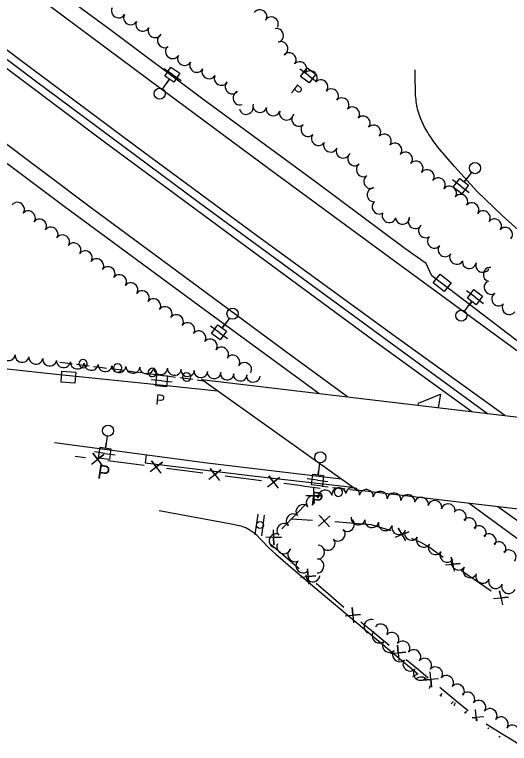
# Model space of a CAD drawing. Extents: x 1746010 to 1754829, y 655801 to 663091.
# Drawn here: x 1750070 to 1750426, y 659823 to 660347 of the extents above; entities that cross this region are included whole.
import ezdxf

# ---------------------------------------------------------------- set-up
doc = ezdxf.new("R2010")
doc.units = 0
for name, color, linetype in [('SURVEY - AERIAL SURVEY - Photo Control - Points - Elevations', 7, 'Continuous'), ('SURVEY - AERIAL SURVEY - Photo Control - Points - Locators', 7, 'Continuous'), ('SURVEY - AERIAL SURVEY - Photo Control - Points - Numbers', 7, 'Continuous'), ('SURVEY - AERIAL SURVEY - Photo Control with Text', 7, 'Continuous'), ('SURVEY - CENTERLINE - Existing Roads - Development', 7, 'Continuous'), ('SURVEY - CENTERLINE - Existing Roads Curve Text', 7, 'Continuous'), ('SURVEY - CENTERLINE - Existing Roads Text', 7, 'Continuous'), ('SURVEY - CENTERLINE - Preliminary - Development', 7, 'Continuous')]:
    doc.layers.add(name, color=color, linetype=linetype)

msp = doc.modelspace()

# ---------------------------------------------------------------- linework, layer by layer
at = {"layer": 'SURVEY - AERIAL SURVEY - Photo Control - Points - Elevations'}
for points in [[(1750204.41, 660084.58), (1750567.39, 660041.45), (1750676.22, 659962.69), (1750316.04, 660004.98)], [(1750316.04, 660004.98), (1750204.41, 660084.58)]]:
    msp.add_lwpolyline(points, dxfattribs=at)
at = {"layer": 'SURVEY - AERIAL SURVEY - Photo Control - Points - Locators'}
for points in [[(1749387.11, 660899.35), (1749486.53, 660821.3), (1749560.37, 660763.13), (1749636.02, 660704.45), (1749732.4, 660629.58), (1749833.07, 660551.99), (1749920.33, 660484.88), (1750008.5, 660418.55), (1750084.45, 660361.56), (1750166.82, 660299.99), (1750252.84, 660236.3), (1750339.47, 660172.61), (1750424.46, 660110.17), (1750505.09, 660051.79), (1750510.03, 660048.27)], [(1750422.34, 660058.69), (1750341.81, 660116.67), (1750243.85, 660188.2), (1750158.07, 660251.54), (1750079.76, 660310), (1749998.95, 660370.82), (1749924.19, 660427.29), (1749840.05, 660491.49), (1749747.97, 660561.59), (1749667.56, 660623.87), (1749593.96, 660681.21), (1749510.38, 660746.53), (1749431.04, 660809.06), (1749359.66, 660865.36)], [(1749353.21, 660856.72), (1749450.09, 660780.53), (1749529.69, 660717.36), (1749638.4, 660632.78), (1749725.25, 660565.49), (1749826.74, 660487.69), (1749908.21, 660425.76), (1750015.78, 660344.74), (1750134.74, 660255.49), (1750241.73, 660176.3), (1750327.29, 660113.27), (1750398.53, 660061.52)], [(1750288.61, 660074.58), (1750206.58, 660134.59), (1750105.78, 660208.88), (1750014.16, 660277.34), (1749883.11, 660375.92), (1749790.93, 660445.43), (1749702.19, 660513.29), (1749634.54, 660565.49), (1749547.88, 660632.78), (1749453.06, 660707.08), (1749311.71, 660816.35)], [(1750309.34, 660072.12), (1750268.26, 660102.16), (1750202.16, 660151.04), (1750125.31, 660207.81), (1750054.71, 660260.76), (1749978.89, 660317.54), (1749904.25, 660374.13), (1749807.5, 660447.32), (1749742.59, 660496.65), (1749689.97, 660537.57), (1749628.45, 660585.34), (1749555.8, 660641.5), (1749484.89, 660697.07), (1749405.47, 660759.79), (1749328.25, 660820.51)], [(1750358.12, 660290), (1750357.98, 660303.43), (1750358.02, 660307.18)], [(1750438.83, 660185.91), (1750420.38, 660202.58), (1750402.21, 660219.96), (1750386.13, 660237.65), (1750374.12, 660251.65)], [(1750519.47, 660047.15), (1750452.55, 660096.14), (1750387.84, 660145.49), (1750369.91, 660159), (1750365.71, 660168.08)], [(1750007.27, 660098.55), (1750097.85, 660088.69), (1750163.16, 660081.99), (1750215.81, 660076.45)], [(1750304.68, 660013.08), (1750208.54, 660024.58), (1750098.73, 660039.05)], [(1750164.64, 660030.36), (1750163.84, 660024.63), (1750243.12, 660015.16), (1750312.84, 660007.26)], [(1750445.81, 659959.59), (1750396.7, 659995.51)], [(1750464.75, 659959.09), (1750428.94, 659984.64), (1750417.4, 659993.08)], [(1750174.01, 659990.42), (1750227.08, 659980.67)], [(1750236.21, 659978.21), (1750238.66, 659976.87), (1750242.86, 659973.96), (1750247.83, 659968.99), (1750252.49, 659963.92), (1750257.85, 659959.09), (1750269.97, 659948.61), (1750288.83, 659932.39), (1750322.85, 659903.93), (1750359.72, 659873.19)], [(1750359.72, 659873.19), (1750355.88, 659870.98)]]:
    msp.add_lwpolyline(points, dxfattribs=at)
for points in [[(1750374.12, 660251.65), (1750366.96, 660262.02), (1750359.66, 660278.87), (1750358.12, 660290)], [(1750227.08, 659980.67), (1750231.41, 659979.69), (1750236.21, 659978.21)]]:
    msp.add_spline(points, degree=3, dxfattribs=at)
at = {"layer": 'SURVEY - AERIAL SURVEY - Photo Control - Points - Numbers'}
for points in [[(1750365.71, 660168.08), (1750350.37, 660178.69), (1750287.2, 660225.82), (1750205.37, 660286.01), (1750139.45, 660335.41), (1750086.68, 660374.49), (1749983.6, 660451.73), (1749923.2, 660497.58), (1749846.86, 660555.87), (1749777.3, 660609.82), (1749717.93, 660655.7), (1749636.62, 660718.64), (1749570.63, 660769.87), (1749510.15, 660817.71), (1749441.97, 660871.04), (1749371.15, 660927.67)], [(1749348.39, 660867.21), (1749450.14, 660787.41), (1749578.82, 660686.52), (1749682.3, 660605.65), (1749779.99, 660530.78), (1749879.01, 660455.62), (1749985.38, 660374.75), (1750084.31, 660300.06), (1750202.67, 660211.89), (1750354.74, 660100.39), (1750409.77, 660060.18)], [(1750106.76, 660096.28), (1750102.61, 660096.79)], [(1750111.43, 660095.69), (1750106.76, 660096.28)], [(1750123.73, 660094.16), (1750114.6, 660095.3)], [(1750131.57, 660093.18), (1750126.91, 660093.76)], [(1750136.24, 660092.6), (1750131.57, 660093.18)], [(1750148.53, 660091.01), (1750139.41, 660092.2)], [(1750156.37, 660089.98), (1750151.71, 660090.59)], [(1750161.03, 660089.37), (1750156.37, 660089.98)], [(1750173.32, 660087.76), (1750164.2, 660088.96)], [(1750181.16, 660086.74), (1750176.5, 660087.35)], [(1750185.81, 660086.13), (1750181.16, 660086.74)], [(1750198.11, 660084.52), (1750188.99, 660085.71)], [(1750205.94, 660083.49), (1750201.28, 660084.1)], [(1750290.74, 660008.01), (1750295.4, 660007.45)], [(1750298.58, 660007.07), (1750307.7, 660005.98)], [(1750310.87, 660005.6), (1750315.54, 660005.05)], [(1750315.54, 660005.05), (1750316.04, 660004.98)]]:
    msp.add_lwpolyline(points, dxfattribs=at)
for centre, start, end in [((1750119.38, 660096.03), 3.5727, 3.5588), ((1750144.22, 660092.9), 3.173, 3.159), ((1750169.01, 660089.65), 3.173, 3.159), ((1750193.8, 660086.41), 3.173, 3.159), ((1750302.74, 660003.55), 196.4762, 196.4622)]:
    msp.add_arc(centre, 3, start, end, dxfattribs=at)
at = {"layer": 'SURVEY - AERIAL SURVEY - Photo Control with Text'}
for p, q in [((1750243, 659972.93), (1750245, 659987.8)), ((1750247.76, 659972.29), (1750249.76, 659987.16))]:
    msp.add_line(p, q, dxfattribs=at)
msp.add_lwpolyline([(1750360.15, 660066.08), (1750360.28, 660067.51), (1750376.1, 660074.16), (1750374.34, 660064.39)], dxfattribs=at)
msp.add_circle((1750246.38, 659980.04), 2.54, dxfattribs=at)
at = {"layer": 'SURVEY - CENTERLINE - Existing Roads - Development'}
for points in [[(1750125.31, 660023.86), (1750134.13, 660030.66), (1750129.77, 660027.26), (1750126.29, 660031.68), (1750133.15, 660022.84)], [(1750113.6, 660029.45), (1750121.16, 660028.47)], [(1750137.12, 660026.4), (1750148.43, 660024.94)], [(1750148.43, 660024.94), (1750163.3, 660023.01)], [(1750167.46, 660018.4), (1750176.27, 660025.21), (1750171.91, 660021.8), (1750168.44, 660026.22), (1750175.29, 660017.39)], [(1750179.26, 660020.95), (1750190.56, 660019.48)], [(1750190.56, 660019.48), (1750205.44, 660017.56)], [(1750209.59, 660012.95), (1750218.41, 660019.75), (1750214.05, 660016.34), (1750210.58, 660020.77), (1750217.43, 660011.93)], [(1750221.4, 660015.49), (1750232.71, 660014.03)], [(1750232.71, 660014.03), (1750247.58, 660012.1)], [(1750251.74, 660007.49), (1750260.55, 660014.3), (1750256.19, 660010.89), (1750252.72, 660015.31), (1750259.57, 660006.48)], [(1750263.54, 660010.03), (1750274.85, 660008.57)], [(1750274.85, 660008.57), (1750278.9, 660008.05), (1750289.7, 660006.61)], [(1750284.85, 660006.54), (1750285.31, 659995.58), (1750285.04, 660001.02), (1750290.68, 660001.13), (1750279.47, 660000.99)], [(1750280.08, 659995.76), (1750272.33, 659987.75)], [(1750272.33, 659987.75), (1750262.12, 659977.21)], [(1750269.14, 659984.45), (1750284.11, 659983.55)], [(1750288.56, 659979.18), (1750296.93, 659986.69), (1750292.79, 659982.93), (1750289.04, 659987.17), (1750296.44, 659978.7)], [(1750300.18, 659982.56), (1750311.55, 659981.66)], [(1750311.55, 659981.66), (1750325.98, 659980.52)], [(1750325.98, 659980.52), (1750338.36, 659976.86), (1750340.31, 659976.17)], [(1750343.61, 659971.21), (1750353.26, 659975.22), (1750348.48, 659973.2), (1750345.81, 659977.85), (1750351.06, 659968.59)], [(1750255.94, 659976.68), (1750256.4, 659965.72), (1750256.13, 659971.17), (1750261.77, 659971.27), (1750250.56, 659971.14)], [(1750355.38, 659970.56), (1750361.73, 659967.77), (1750365.58, 659965.55)], [(1750254.54, 659966.02), (1750263.16, 659958.56)], [(1750365.58, 659965.55), (1750368.24, 659964.01), (1750377.91, 659957.05)], [(1750263.16, 659958.56), (1750274.51, 659948.76)], [(1750379.58, 659951.44), (1750390.18, 659952.41), (1750384.92, 659951.9), (1750383.77, 659957.03), (1750385.99, 659946.83)], [(1750275.41, 659942.62), (1750286.57, 659943.43), (1750281.03, 659942.99), (1750280.6, 659948.6), (1750281.39, 659937.45)], [(1750390.97, 659947.65), (1750395.32, 659944.52), (1750400.28, 659941.11)], [(1750400.28, 659941.11), (1750412.58, 659932.64)], [(1750286.7, 659938.23), (1750295.32, 659930.77)], [(1750295.32, 659930.77), (1750306.67, 659920.97)], [(1750414.27, 659927.15), (1750425, 659928.23), (1750419.67, 659927.66), (1750418.51, 659932.69), (1750420.75, 659922.69)], [(1750307.57, 659914.83), (1750318.73, 659915.64), (1750313.19, 659915.2), (1750312.75, 659920.81), (1750313.55, 659909.66)], [(1750318.88, 659910.49), (1750327.62, 659903.25)], [(1750327.62, 659903.25), (1750339.12, 659893.72)], [(1750340.09, 659887.65), (1750351.28, 659888.66), (1750345.72, 659888.12), (1750345.22, 659893.68), (1750346.14, 659882.64)], [(1750351.46, 659883.5), (1750360.2, 659876.26)], [(1750360.2, 659876.26), (1750367.35, 659870.33)], [(1750374.69, 659869.54), (1750363.49, 659868.48), (1750369.05, 659869.04), (1750369.55, 659863.41), (1750368.63, 659874.61)], [(1750387.16, 659853.77), (1750375.66, 659863.39)], [(1750395.91, 659846.46), (1750387.16, 659853.77)], [(1750401.88, 659839.37), (1750401.22, 659847.36)], [(1750398.78, 659841.5), (1750401.65, 659841.79), (1750401.86, 659839.38)], [(1750407.28, 659842.29), (1750398.8, 659841.48)], [(1750421.64, 659829.1), (1750408.88, 659836.99)], [(1750431.32, 659823.1), (1750425.59, 659826.66), (1750421.64, 659829.1)]]:
    msp.add_lwpolyline(points, dxfattribs=at)
at = {"layer": 'SURVEY - CENTERLINE - Existing Roads Curve Text'}
for p, q in [((1750183.51, 660303.76), (1750177.27, 660307.93)), ((1750280.98, 660303.2), (1750274.99, 660307.73)), ((1750183.51, 660303.76), (1750189.74, 660299.59)), ((1750280.98, 660303.2), (1750286.96, 660298.68)), ((1750176.5, 660293.28), (1750181.34, 660300.52)), ((1750181.12, 660300.19), (1750179.34, 660297.52)), ((1750398.47, 660233.43), (1750393.15, 660226.54)), ((1750393.4, 660226.86), (1750395.35, 660229.39)), ((1750390.77, 660223.46), (1750384.83, 660228.04)), ((1750390.77, 660223.46), (1750396.71, 660218.87)), ((1750400.9, 660143.73), (1750394.89, 660148.22)), ((1750393.36, 660133.63), (1750398.57, 660140.61)), ((1750398.33, 660140.29), (1750396.41, 660137.72)), ((1750400.9, 660143.73), (1750406.91, 660139.25)), ((1750224.42, 660128.69), (1750219.32, 660121.65)), ((1750219.55, 660121.97), (1750221.43, 660124.56)), ((1750217.03, 660118.49), (1750210.95, 660122.89)), ((1750217.03, 660118.49), (1750223.1, 660114.09)), ((1750175.8, 660083.64), (1750168.33, 660084.33)), ((1750175.8, 660083.64), (1750183.27, 660082.95)), ((1750136.74, 660043.97), (1750135.5, 660035.36)), ((1750135.56, 660035.75), (1750136.01, 660038.92)), ((1750134.94, 660031.5), (1750127.52, 660032.57)), ((1750134.94, 660031.5), (1750142.37, 660030.42)), ((1750289.27, 660024.78), (1750288.26, 660016.14)), ((1750288.3, 660016.54), (1750288.68, 660019.72)), ((1750287.8, 660012.27), (1750280.35, 660013.14)), ((1750287.8, 660012.27), (1750295.25, 660011.39))]:
    msp.add_line(p, q, dxfattribs=at)
for points in [[(1750188.92, 660304.83), (1750184.58, 660298.35), (1750178.09, 660302.69), (1750182.43, 660309.17)], [(1750280.22, 660308.67), (1750286.44, 660303.96), (1750281.74, 660297.74), (1750275.51, 660302.44)], [(1750385.3, 660222.76), (1750390.07, 660228.93), (1750396.24, 660224.16), (1750391.47, 660217.99)], [(1750406.36, 660144.53), (1750401.69, 660138.28), (1750395.44, 660142.94), (1750400.11, 660149.19)], [(1750211.58, 660117.62), (1750216.16, 660123.94), (1750222.48, 660119.36), (1750217.9, 660113.04)], [(1750172.28, 660087.88), (1750180.04, 660087.17), (1750179.33, 660079.4), (1750171.56, 660080.11)], [(1750130.53, 660028.19), (1750131.64, 660035.91), (1750139.36, 660034.8), (1750138.25, 660027.08)], [(1750283.47, 660008.85), (1750284.38, 660016.6), (1750292.13, 660015.69), (1750291.22, 660007.94)]]:
    msp.add_lwpolyline(points, close=True, dxfattribs=at)
for centre in [(1750174.33, 660290.04), (1750400.86, 660236.52), (1750226.71, 660131.85), (1750391.03, 660130.51), (1750137.3, 660047.83), (1750289.73, 660028.66)]:
    msp.add_circle(centre, 4, dxfattribs=at)
at = {"layer": 'SURVEY - CENTERLINE - Existing Roads Text'}
for centre, major_axis, start_param, end_param in [((1750144.65, 660349.24), (-4.35, 2.46), 0, 3.141593), ((1750246.46, 660345.55), (4.23, -2.67), 0, 3.141593), ((1750153.35, 660344.32), (-4.35, 2.46), 0, 3.141593), ((1750254.66, 660340.37), (4.23, -2.67), 0, 3.141593), ((1750162.15, 660339.63), (-4.44, 2.3), 0, 3.141593), ((1750170.99, 660335.05), (-4.44, 2.3), 0, 3.141593), ((1750258.52, 660331.86), (1.24, -4.84), 0, 3.141593), ((1750177.61, 660327.97), (-2.74, 4.18), 0, 3.141593), ((1750261.74, 660322.51), (2.12, -4.53), 0, 3.141593), ((1750183.44, 660319.97), (-4.35, 2.46), 0, 3.141593), ((1750267.53, 660314.64), (3.8, -3.25), 0, 3.141593), ((1750192.14, 660315.06), (-4.35, 2.46), 0, 3.141593), ((1750200.85, 660310.14), (-4.35, 2.46), 0, 3.141593), ((1750275.13, 660308.14), (3.8, -3.25), 0, 3.141593), ((1750209.65, 660305.45), (-4.43, 2.33), 0, 3.141593), ((1750218.48, 660300.81), (-4.43, 2.33), 0, 3.141593), ((1750282.72, 660301.64), (3.8, -3.25), 0, 3.141593), ((1750226.35, 660294.71), (-3.81, 3.24), 0, 3.141593), ((1750290.32, 660295.13), (3.8, -3.25), 0, 3.141593), ((1750297.91, 660288.63), (3.8, -3.25), 0, 3.141593), ((1750231.81, 660286.85), (-1.83, 4.65), 0, 3.141593), ((1750305.51, 660282.13), (3.8, -3.25), 0, 3.141593), ((1750246.26, 660281.21), (-4.85, 1.21), 0, 3.141593), ((1750236.54, 660279.86), (-4.89, -1.05), 0, 3.141593), ((1750255.9, 660278.79), (-4.85, 1.21), 0, 3.141593), ((1750265.35, 660275.79), (-4.71, 1.69), 0, 3.141593), ((1750313.1, 660275.63), (3.8, -3.25), 0, 3.141593), ((1750274.07, 660271.5), (-3.34, 3.72), 0, 3.141593), ((1750320.7, 660269.13), (3.8, -3.25), 0, 3.141593), ((1750280.74, 660264.06), (-3.34, 3.72), 0, 3.141593), ((1750328.3, 660262.64), (3.8, -3.25), 0, 3.141593), ((1750288.3, 660257.53), (-3.87, 3.17), 0, 3.141593), ((1750335.9, 660256.15), (3.8, -3.25), 0, 3.141593), ((1750297.05, 660252.81), (-4.53, 2.11), 0, 3.141593), ((1750343.5, 660249.66), (3.8, -3.25), 0, 3.141593), ((1750306.04, 660248.46), (-4.37, 2.44), 0, 3.141593), ((1750314.27, 660243.08), (-3.11, 3.92), 0, 3.141593), ((1750351.1, 660243.17), (3.8, -3.25), 0, 3.141593), ((1750320.42, 660235.2), (-2.67, 4.23), 0, 3.141593), ((1750358.71, 660236.68), (3.8, -3.25), 0, 3.141593), ((1750366.64, 660230.6), (4.03, -2.97), 0, 3.141593), ((1750325.76, 660226.75), (-2.67, 4.23), 0, 3.141593), ((1750374.69, 660224.67), (4.03, -2.97), 0, 3.141593), ((1750382.74, 660218.74), (4.03, -2.97), 0, 3.141593), ((1750328.17, 660217.28), (-0.7, 4.95), 0, 3.141593), ((1750390.79, 660212.81), (4.03, -2.97), 0, 3.141593), ((1750072.33, 660207.14), (3.93, -3.1), 0, 3.141593), ((1750331.84, 660208.38), (-3.05, 3.96), 0, 3.141593), ((1750398.85, 660206.9), (4.05, -2.93), 0, 3.141593), ((1750080.19, 660200.95), (3.93, -3.1), 0, 3.141593), ((1750339.17, 660202.09), (-4.63, 1.89), 0, 3.141593), ((1750406.94, 660201.05), (4.05, -2.93), 0, 3.141593), ((1750088.26, 660195.07), (4.11, -2.85), 0, 3.141593), ((1750348.88, 660200.95), (-5, -0.22), 0, 3.141593), ((1750357.85, 660197.8), (-4.24, 2.66), 0, 3.141593), ((1750415.03, 660195.2), (4.05, -2.93), 0, 3.141593), ((1750096.46, 660189.38), (4.11, -2.85), 0, 3.141593), ((1750365.15, 660191.36), (-2.94, 4.05), 0, 3.141593), ((1750422.94, 660189.11), (3.75, -3.3), 0, 3.141593), ((1750104.66, 660183.68), (4.11, -2.85), 0, 3.141593), ((1750371.52, 660183.84), (-3.91, 3.12), 0, 3.141593), ((1750112.86, 660177.98), (4.11, -2.85), 0, 3.141593), ((1750121.07, 660172.29), (4.11, -2.85), 0, 3.141593), ((1750379.24, 660177.67), (-3.91, 3.12), 0, 3.141593), ((1750129.26, 660166.57), (4.09, -2.87), 0, 3.141593), ((1750387.54, 660172.15), (-4.18, 2.75), 0, 3.141593), ((1750137.44, 660160.83), (4.09, -2.87), 0, 3.141593), ((1750396.79, 660169.02), (-4.92, 0.88), 0, 3.141593), ((1750406.32, 660166.37), (-4.57, 2.03), 0, 3.141593), ((1750411.56, 660160.15), (0.64, 4.96), 0, 3.141593), ((1750145.63, 660155.09), (4.09, -2.87), 0, 3.141593), ((1750153.82, 660149.35), (4.09, -2.87), 0, 3.141593), ((1750412.28, 660150.71), (-2.75, 4.18), 0, 3.141593), ((1750162.01, 660143.62), (4.09, -2.87), 0, 3.141593), ((1750417.75, 660142.38), (-2.75, 4.18), 0, 3.141593), ((1750170.19, 660137.88), (4.09, -2.87), 0, 3.141593), ((1750178.38, 660132.14), (4.09, -2.87), 0, 3.141593), ((1750425.35, 660136.09), (-4.11, 2.85), 0, 3.141593), ((1750186.52, 660126.36), (4.06, -2.92), 0, 3.141593), ((1750194.62, 660120.54), (4.06, -2.92), 0, 3.141593), ((1750202.72, 660114.72), (4.06, -2.92), 0, 3.141593), ((1750210.81, 660108.89), (4.06, -2.92), 0, 3.141593), ((1750218.91, 660103.07), (4.06, -2.92), 0, 3.141593), ((1750065.62, 660102.96), (-4.96, 0.66), 0, 3.141593), ((1750075.53, 660101.65), (-4.96, 0.66), 0, 3.141593), ((1750085.43, 660100.34), (-4.96, 0.66), 0, 3.141593), ((1750095.34, 660099.03), (-4.96, 0.66), 0, 3.141593), ((1750105.26, 660097.85), (-4.98, 0.48), 0, 3.141593), ((1750227.03, 660097.29), (4.23, -2.67), 0, 3.141593), ((1750115.22, 660096.88), (-4.98, 0.48), 0, 3.141593), ((1750125.17, 660095.91), (-4.98, 0.48), 0, 3.141593), ((1750135.12, 660094.95), (-4.98, 0.48), 0, 3.141593), ((1750145.1, 660094.27), (-4.99, 0.23), 0, 3.141593), ((1750155.08, 660093.8), (-4.99, 0.23), 0, 3.141593), ((1750165.07, 660093.34), (-4.99, 0.23), 0, 3.141593), ((1750175.06, 660092.88), (-4.99, 0.23), 0, 3.141593), ((1750184.93, 660092.34), (-4.98, 0.42), 0, 3.141593), ((1750235.46, 660091.98), (4.23, -2.67), 0, 3.141593), ((1750194.45, 660091.54), (-4.98, 0.42), 0, 3.141593), ((1750203.98, 660090.75), (-4.98, 0.42), 0, 3.141593), ((1750213.5, 660089.96), (-4.98, 0.42), 0, 3.141593), ((1750222.9, 660089.13), (-4.98, 0.45), 0, 3.141593), ((1750232.25, 660088.29), (-4.98, 0.45), 0, 3.141593), ((1750241.6, 660087.46), (-4.98, 0.45), 0, 3.141593), ((1750293.23, 660000.42), (4.93, 0.86), 0, 3.141593), ((1750303.08, 660002.15), (4.93, 0.86), 0, 3.141593), ((1750312.97, 660002.09), (4.96, -0.63), 0, 3.141593), ((1750322.89, 660000.83), (4.96, -0.63), 0, 3.141593), ((1750332.81, 659999.57), (4.96, -0.63), 0, 3.141593), ((1750284.57, 659996.37), (3.76, 3.3), 0, 3.141593), ((1750342.73, 659998.31), (4.96, -0.63), 0, 3.141593), ((1750352.65, 659997.05), (4.96, -0.63), 0, 3.141593), ((1750362.4, 659995.19), (4.86, -1.17), 0, 3.141593), ((1750277.14, 659989.86), (3.76, 3.3), 0, 3.141593), ((1750372.02, 659992.88), (4.86, -1.17), 0, 3.141593), ((1750381.65, 659990.57), (4.86, -1.17), 0, 3.141593), ((1750270.05, 659983.19), (3.45, 3.62), 0, 3.141593), ((1750389.73, 659986.13), (3.9, -3.13), 0, 3.141593), ((1750309.4, 659980.32), (-3.39, -3.68), 0, 3.141593), ((1750316.89, 659984.76), (-4.91, 0.93), 0, 3.141593), ((1750326.71, 659982.9), (-4.91, 0.93), 0, 3.141593), ((1750396.87, 659980.4), (3.9, -3.13), 0, 3.141593), ((1750263.47, 659976.27), (3.45, 3.62), 0, 3.141593), ((1750336.46, 659980.72), (-4.81, 1.37), 0, 3.141593), ((1750346.08, 659977.97), (-4.81, 1.37), 0, 3.141593), ((1750404.01, 659974.66), (3.9, -3.13), 0, 3.141593), ((1750257.76, 659968.78), (1.76, 4.68), 0, 3.141593), ((1750302.72, 659973.35), (-3.68, -3.39), 0, 3.141593), ((1750355.12, 659973.88), (-4.32, 2.51), 0, 3.141593), ((1750411.15, 659968.92), (3.9, -3.13), 0, 3.141593), ((1750295.48, 659966.71), (-4.05, -2.93), 0, 3.141593), ((1750363.77, 659968.86), (-4.32, 2.51), 0, 3.141593), ((1750418.29, 659963.18), (3.9, -3.13), 0, 3.141593), ((1750263.37, 659964.2), (-4.4, 2.37), 0, 3.141593), ((1750271.26, 659958.55), (-2.73, 4.19), 0, 3.141593), ((1750288.02, 659960.52), (-0.2, -5), 0, 3.141593), ((1750372.25, 659963.57), (-4.16, 2.77), 0, 3.141593), ((1750425.51, 659957.29), (3.84, -3.2), 0, 3.141593), ((1750380.57, 659958.03), (-4.16, 2.77), 0, 3.141593), ((1750277.14, 659950.52), (-3.51, 3.56), 0, 3.141593), ((1750287.63, 659950.67), (-0.2, -5), 0, 3.141593), ((1750388.9, 659952.49), (-4.16, 2.77), 0, 3.141593), ((1750397.22, 659946.95), (-4.16, 2.77), 0, 3.141593), ((1750284.4, 659943.95), (-4.99, 0.36), 0, 3.141593), ((1750406.4, 659943.01), (-4.61, 1.94), 0, 3.141593), ((1750415.63, 659939.17), (-4.67, 1.8), 0, 3.141593), ((1750424.96, 659935.57), (-4.67, 1.8), 0, 3.141593), ((1750325.94, 659907.2), (1.99, 4.59), 0, 3.141593), ((1750333.44, 659904.08), (4.12, -2.83), 0, 3.141593), ((1750331.85, 659900.13), (-3.67, 3.39), 0, 3.141593), ((1750341.4, 659898.05), (3.92, -3.1), 0, 3.141593), ((1750339.18, 659893.35), (-3.67, 3.39), 0, 3.141593), ((1750349.23, 659891.85), (3.92, -3.1), 0, 3.141593), ((1750346.53, 659886.59), (-3.73, 3.33), 0, 3.141593), ((1750357.06, 659885.66), (3.92, -3.1), 0, 3.141593), ((1750353.99, 659879.94), (-3.73, 3.33), 0, 3.141593), ((1750364.89, 659879.47), (3.92, -3.1), 0, 3.141593), ((1750372.72, 659873.27), (3.92, -3.1), 0, 3.141593), ((1750361.45, 659873.28), (-3.73, 3.33), 0, 3.141593), ((1750361.95, 659866.04), (4.23, 2.67), 0, 1.807456), ((1750380.55, 659867.08), (3.92, -3.1), 0, 3.141593), ((1750372.94, 659861.67), (-4.15, 2.79), 0, 0.43278), ((1750388.38, 659860.88), (3.92, -3.1), 0, 3.141593), ((1750372.94, 659861.67), (-4.15, 2.79), 2.68791, 3.141593), ((1750381.21, 659856.1), (-4.15, 2.79), 0, 0.456042), ((1750395.78, 659855.23), (4.02, -2.98), 0, 3.141593), ((1750381.21, 659856.1), (-4.15, 2.79), 2.664647, 3.141593), ((1750390.69, 659849.28), (-3.99, 3.01), 0, 0.508212), ((1750403.81, 659849.28), (4.02, -2.98), 0, 3.141593), ((1750411.84, 659843.32), (4.02, -2.98), 0, 3.141593), ((1750390.69, 659849.28), (-3.99, 3.01), 2.740087, 3.141593), ((1750398.66, 659843.27), (-3.99, 3.01), 0, 0.392473), ((1750419.88, 659837.37), (4.02, -2.98), 0, 3.141593), ((1750398.66, 659843.27), (-3.99, 3.01), 2.855841, 3.141593), ((1750406.64, 659837.26), (-4.02, 2.97), 0, 0.271904), ((1750427.92, 659831.42), (4.22, -2.68), 0, 3.141593), ((1750406.64, 659837.26), (-4.02, 2.97), 2.94098, 3.141593), ((1750414.68, 659831.31), (-4.02, 2.97), 0, 0.201411), ((1750414.68, 659831.31), (-4.02, 2.97), 2.901417, 3.141593), ((1750422.72, 659825.37), (-4.02, 2.97), 0, 0.241326)]:
    msp.add_ellipse(centre, major_axis=major_axis, ratio=0.940188, start_param=start_param, end_param=end_param, dxfattribs=at)
at = {"layer": 'SURVEY - CENTERLINE - Preliminary - Development'}
for p, q in [((1750377.28, 660154.11), (1750377.28, 660154.11)), ((1750108.82, 660086.26), (1750108.82, 660086.26))]:
    msp.add_line(p, q, dxfattribs=at)
for points in [[(1750370.88, 660154.14), (1750375.91, 660160.36), (1750383.69, 660154.08), (1750378.66, 660147.86), (1750370.88, 660154.14)], [(1750103.52, 660082.67), (1750104.16, 660090.64), (1750114.13, 660089.84), (1750113.49, 660081.87), (1750103.52, 660082.67)]]:
    msp.add_lwpolyline(points, dxfattribs=at)

# ---------------------------------------------------------------- texts
at = {"layer": 'SURVEY - CENTERLINE - Existing Roads Curve Text'}
for height, rotation, p in [(7.48, 322.9107, (1750268.07, 660291.27)), (7.48, 354.7524, (1750171.13, 660066.69)), (10, 351.7871, (1750129.13, 660013.64)), (10, 353.3009, (1750282.47, 659994.27))]:
    msp.add_text('P', height=height, rotation=rotation, dxfattribs=at).set_placement(p)

doc.saveas('drawing.dxf')
